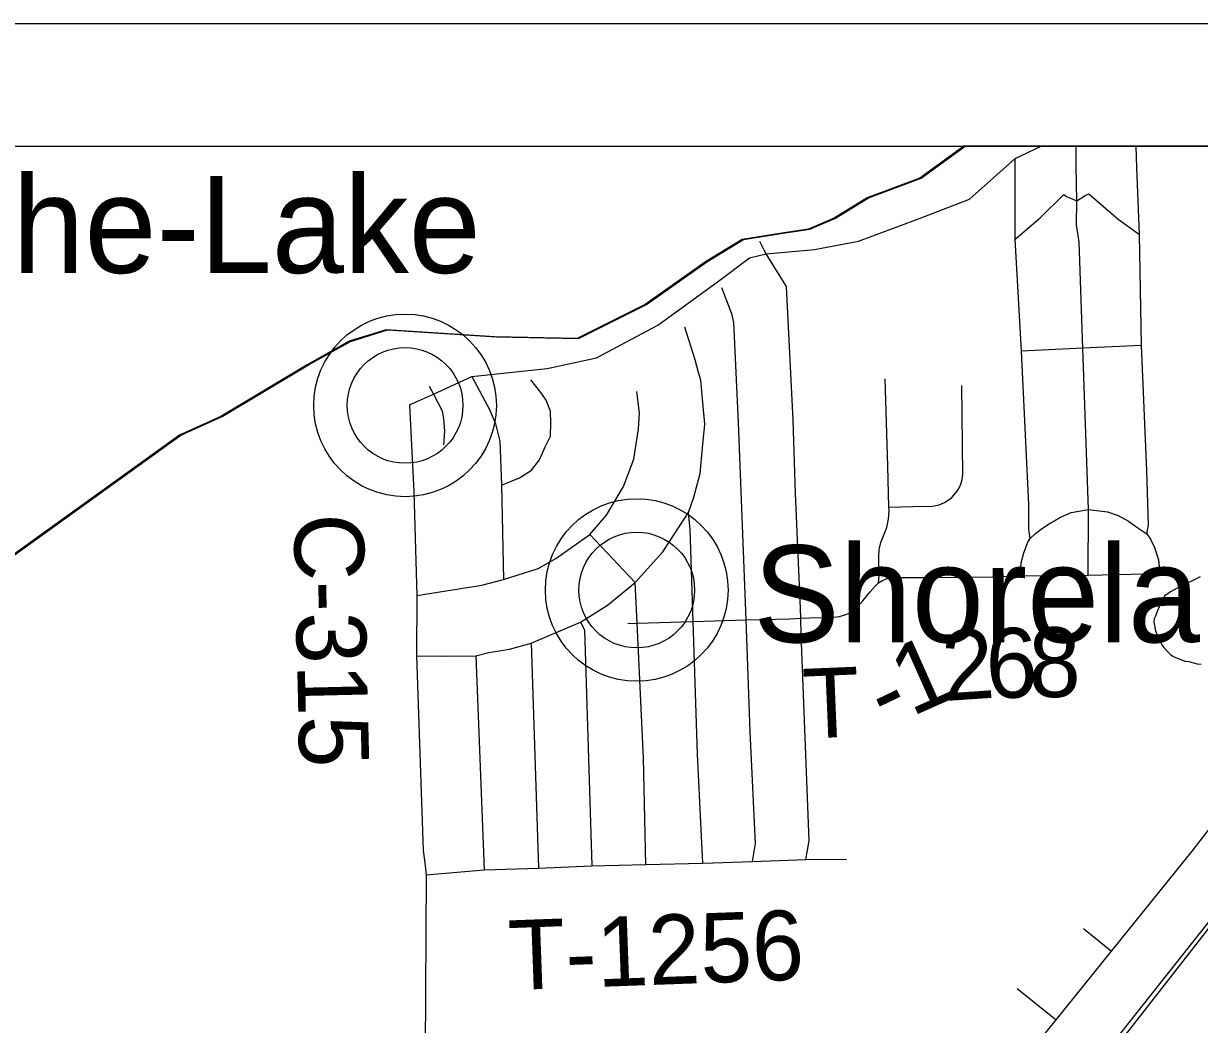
# Model space of a CAD drawing. Extents: x -59 to 82, y -3 to 49.
# Drawn here: x -52.99 to -52.032, y 48.576 to 49.391 of the extents above; entities that cross this region are included whole.
import ezdxf

# ---------------------------------------------------------------- set-up
doc = ezdxf.new("R2010")
doc.units = 0
for name, color, linetype in [('GM_X_Corporation', 7, 'Continuous'), ('GM_X_County_Road_Text', 7, 'Continuous'), ('GM_X_Major_Lake', 7, 'Continuous'), ('GM_X_Minor_River', 7, 'Continuous'), ('GM_X_Rail_Line', 7, 'Continuous'), ('GM_X_Township_Road', 7, 'Continuous'), ('GM_X_Township_Road_Text', 7, 'Continuous'), ('GM_X_Unincorporated', 7, 'Continuous'), ('GM_X_Unincorporated_Location', 7, 'Continuous'), ('GM_X_Unincorporated_Text', 7, 'Continuous'), ('SH_Data', 7, 'Continuous')]:
    doc.layers.add(name, color=color, linetype=linetype)

msp = doc.modelspace()

# ---------------------------------------------------------------- linework, layer by layer
at = {"layer": 'GM_X_Corporation'}
for p, q in [((-52.22423, 49.29125), (-52.26009, 49.26516)), ((-52.22423, 49.29125), (-52.26009, 49.26516)), ((-48.09799, 49.29125), (-52.22423, 49.29125)), ((-50.61637, 49.29125), (-52.22423, 49.29125)), ((-52.26009, 49.26516), (-52.30287, 49.24915)), ((-52.26009, 49.26516), (-52.30287, 49.24915)), ((-52.30287, 49.24915), (-52.32966, 49.23263)), ((-52.30287, 49.24915), (-52.32966, 49.23263)), ((-52.32966, 49.23263), (-52.35068, 49.22367)), ((-52.32966, 49.23263), (-52.35068, 49.22367)), ((-52.37241, 49.22042), (-52.40482, 49.21534)), ((-52.37241, 49.22042), (-52.40482, 49.21534)), ((-52.35068, 49.22367), (-52.37241, 49.22042)), ((-52.35068, 49.22367), (-52.37241, 49.22042)), ((-52.40482, 49.21534), (-52.43467, 49.19695)), ((-52.40482, 49.21534), (-52.43467, 49.19695)), ((-52.43467, 49.19695), (-52.4837, 49.16236)), ((-52.43467, 49.19695), (-52.4837, 49.16236)), ((-52.4837, 49.16236), (-52.53915, 49.13466)), ((-52.4837, 49.16236), (-52.53915, 49.13466)), ((-52.69484, 49.14154), (-52.725, 49.13227)), ((-52.69484, 49.14154), (-52.725, 49.13227)), ((-52.60615, 49.13593), (-52.69484, 49.14154)), ((-52.60615, 49.13593), (-52.69484, 49.14154)), ((-52.53915, 49.13466), (-52.60615, 49.13593)), ((-52.53915, 49.13466), (-52.60615, 49.13593)), ((-52.725, 49.13227), (-52.75904, 49.11315)), ((-52.725, 49.13227), (-52.75904, 49.11315)), ((-52.75904, 49.11315), (-52.82946, 49.07112)), ((-52.75904, 49.11315), (-52.82946, 49.07112)), ((-52.82946, 49.07112), (-52.86309, 49.0558)), ((-52.82946, 49.07112), (-52.86309, 49.0558)), ((-52.86309, 49.0558), (-53.01862, 48.94411)), ((-52.86309, 49.0558), (-53.01862, 48.94411))]:
    msp.add_line(p, q, dxfattribs=at)
at = {"layer": 'GM_X_Major_Lake'}
for p, q in [((-52.25901, 49.26513), (-52.22309, 49.29125)), ((-52.30179, 49.24911), (-52.25901, 49.26513)), ((-52.32858, 49.23259), (-52.30179, 49.24911)), ((-52.3496, 49.22363), (-52.32858, 49.23259)), ((-52.40374, 49.2153), (-52.37133, 49.22038)), ((-52.37133, 49.22038), (-52.3496, 49.22363)), ((-52.43359, 49.19691), (-52.40374, 49.2153)), ((-52.48262, 49.16232), (-52.43359, 49.19691)), ((-52.53807, 49.13462), (-52.48262, 49.16232)), ((-52.72392, 49.13223), (-52.69376, 49.1415)), ((-52.69376, 49.1415), (-52.60508, 49.13589)), ((-52.60508, 49.13589), (-52.53807, 49.13462)), ((-52.75796, 49.11311), (-52.72392, 49.13223)), ((-52.82838, 49.07108), (-52.75796, 49.11311)), ((-52.86201, 49.05576), (-52.82838, 49.07108)), ((-53.01754, 48.94407), (-52.86201, 49.05576))]:
    msp.add_line(p, q, dxfattribs=at)
at = {"layer": 'GM_X_Minor_River'}
for p, q in [((-52.04363, 48.93436), (-52.0474, 48.93238)), ((-52.03156, 48.94031), (-52.04363, 48.93436)), ((-52.05871, 48.92607), (-52.06096, 48.9245)), ((-52.06096, 48.9245), (-52.06092, 48.92222)), ((-52.0557, 48.92803), (-52.05871, 48.92607)), ((-52.05268, 48.92961), (-52.0557, 48.92803)), ((-52.05043, 48.93118), (-52.05268, 48.92961)), ((-52.0474, 48.93238), (-52.05043, 48.93118)), ((-52.0657, 48.91414), (-52.06787, 48.90839)), ((-52.06424, 48.91721), (-52.0657, 48.91414)), ((-52.06092, 48.92222), (-52.06424, 48.91721)), ((-52.06897, 48.90609), (-52.0693, 48.90342)), ((-52.06787, 48.90839), (-52.06897, 48.90609)), ((-52.0693, 48.90342), (-52.06801, 48.89622)), ((-52.06801, 48.89622), (-52.0664, 48.89207)), ((-52.0664, 48.89207), (-52.06282, 48.88492)), ((-52.06282, 48.88492), (-52.06125, 48.88267)), ((-52.06125, 48.88267), (-52.05852, 48.87969)), ((-52.05852, 48.87969), (-52.0558, 48.87709)), ((-52.0558, 48.87709), (-52.05386, 48.8756)), ((-52.05386, 48.8756), (-52.05156, 48.87451)), ((-52.05156, 48.87451), (-52.04388, 48.87163)), ((-52.04388, 48.87163), (-52.04082, 48.87131)), ((-52.04082, 48.87131), (-52.03699, 48.87025)), ((-52.03699, 48.87025), (-52.03393, 48.86955)), ((-52.03393, 48.86955), (-52.03087, 48.86923))]:
    msp.add_line(p, q, dxfattribs=at)
at = {"layer": 'GM_X_Rail_Line'}
for p, q in [((-52.14781, 48.49604), (-51.94583, 48.75479)), ((-52.14538, 48.50651), (-51.96248, 48.7375))]:
    msp.add_line(p, q, dxfattribs=at)
at = {"layer": 'GM_X_Township_Road'}
for p, q in [((-52.18239, 49.28132), (-52.16098, 49.29125)), ((-52.13271, 49.29092), (-52.13278, 49.29125)), ((-52.13247, 49.27499), (-52.13271, 49.29092)), ((-52.08311, 49.27362), (-52.08377, 49.29125)), ((-52.21959, 49.2482), (-52.18239, 49.28132)), ((-52.18231, 49.2319), (-52.18239, 49.28132)), ((-52.13206, 49.24687), (-52.13247, 49.27499)), ((-52.08108, 49.21933), (-52.08311, 49.27362)), ((-52.16187, 49.2328), (-52.1426, 49.25183)), ((-52.1426, 49.25183), (-52.14036, 49.25039)), ((-52.14036, 49.25039), (-52.13206, 49.24687)), ((-52.13206, 49.24687), (-52.12535, 49.25103)), ((-52.12535, 49.25103), (-52.12234, 49.25235)), ((-52.12234, 49.25235), (-52.09845, 49.23193)), ((-52.26312, 49.23127), (-52.21959, 49.2482)), ((-52.13234, 49.22715), (-52.13206, 49.24687)), ((-52.31003, 49.21385), (-52.26312, 49.23127)), ((-52.18228, 49.21542), (-52.18231, 49.2319)), ((-52.18228, 49.21542), (-52.16187, 49.2328)), ((-52.09845, 49.23193), (-52.08108, 49.21933)), ((-52.13016, 49.21325), (-52.13234, 49.22715)), ((-52.38687, 49.20663), (-52.39026, 49.21351)), ((-52.34583, 49.20708), (-52.31003, 49.21385)), ((-52.17707, 49.12419), (-52.18228, 49.21542)), ((-52.12714, 49.12663), (-52.13016, 49.21325)), ((-52.07934, 49.12896), (-52.08108, 49.21933)), ((-52.39878, 49.20035), (-52.38505, 49.20368)), ((-52.38505, 49.20368), (-52.38687, 49.20663)), ((-52.38505, 49.20368), (-52.34583, 49.20708)), ((-52.36914, 49.17778), (-52.38505, 49.20368)), ((-52.42293, 49.18215), (-52.39878, 49.20035)), ((-52.47332, 49.14539), (-52.42293, 49.18215)), ((-52.41275, 49.15392), (-52.42137, 49.17573)), ((-52.36861, 49.17691), (-52.36914, 49.17778)), ((-52.36311, 49.06792), (-52.36861, 49.17691)), ((-52.41144, 49.14758), (-52.41275, 49.15392)), ((-52.52337, 49.11879), (-52.47332, 49.14539)), ((-52.44314, 49.11711), (-52.45137, 49.1437)), ((-52.40779, 49.06611), (-52.41144, 49.14758)), ((-52.12714, 49.12663), (-52.17707, 49.12419)), ((-52.17116, 48.9993), (-52.17707, 49.12419)), ((-52.07934, 49.12896), (-52.12714, 49.12663)), ((-52.12256, 48.99533), (-52.12714, 49.12663)), ((-52.07509, 49.02692), (-52.07934, 49.12896)), ((-52.56361, 49.11004), (-52.52337, 49.11879)), ((-52.44032, 49.10695), (-52.44314, 49.11711)), ((-52.62496, 49.1036), (-52.56361, 49.11004)), ((-52.43853, 49.10048), (-52.44032, 49.10695)), ((-52.65974, 49.09578), (-52.65635, 49.0893)), ((-52.65635, 49.0893), (-52.62496, 49.1036)), ((-52.62496, 49.1036), (-52.61041, 49.0761)), ((-52.5689, 49.09066), (-52.57694, 49.10093)), ((-52.43673, 49.08239), (-52.43853, 49.10048)), ((-52.28609, 49.03048), (-52.28823, 49.10182)), ((-52.22484, 49.02382), (-52.22575, 49.09616)), ((-52.67584, 49.08043), (-52.65635, 49.0893)), ((-52.65635, 49.0893), (-52.64924, 49.07571)), ((-52.56489, 49.08499), (-52.5689, 49.09066)), ((-52.48844, 49.07362), (-52.49056, 49.09128)), ((-52.67584, 49.08043), (-52.6722, 49.00961)), ((-52.56432, 49.08418), (-52.56489, 49.08499)), ((-52.56081, 49.07528), (-52.56432, 49.08418)), ((-52.43518, 49.06482), (-52.43673, 49.08239)), ((-52.64924, 49.07571), (-52.64809, 49.06903)), ((-52.64809, 49.06903), (-52.64717, 49.05913)), ((-52.61041, 49.0761), (-52.60583, 49.06504)), ((-52.56055, 49.06585), (-52.56081, 49.07528)), ((-52.48915, 49.0609), (-52.48844, 49.07362)), ((-52.3614, 49.00834), (-52.36311, 49.06792)), ((-52.64717, 49.05913), (-52.6481, 49.04784)), ((-52.60583, 49.06504), (-52.60205, 49.05102)), ((-52.56081, 49.05506), (-52.56055, 49.06585)), ((-52.49303, 49.03617), (-52.48915, 49.0609)), ((-52.43699, 49.04544), (-52.43518, 49.06482)), ((-52.40152, 48.90541), (-52.40779, 49.06611)), ((-52.60205, 49.05102), (-52.60071, 49.01517)), ((-52.56513, 49.04617), (-52.56081, 49.05506)), ((-52.56998, 49.03565), (-52.56513, 49.04617)), ((-52.43905, 49.02451), (-52.43699, 49.04544)), ((-52.57645, 49.0273), (-52.56998, 49.03565)), ((-52.50151, 49.01391), (-52.49303, 49.03617)), ((-52.2851, 48.99715), (-52.28609, 49.03048)), ((-52.60071, 49.01517), (-52.58615, 49.02109)), ((-52.58615, 49.02109), (-52.57645, 49.0273)), ((-52.44422, 49.00539), (-52.43905, 49.02451)), ((-52.22667, 49.01576), (-52.22547, 49.01966)), ((-52.22547, 49.01966), (-52.22484, 49.02382)), ((-52.07358, 48.98266), (-52.07509, 49.02692)), ((-52.6722, 49.00961), (-52.66968, 48.92502)), ((-52.60071, 49.01517), (-52.59908, 48.93805)), ((-52.51528, 48.9906), (-52.50151, 49.01391)), ((-52.23065, 49.00868), (-52.22855, 49.01181)), ((-52.22855, 49.01181), (-52.22667, 49.01576)), ((-52.44835, 48.99273), (-52.44422, 49.00539)), ((-52.35723, 48.91459), (-52.3614, 49.00834)), ((-52.24413, 48.99907), (-52.23993, 49.00087)), ((-52.23993, 49.00087), (-52.23682, 49.00277)), ((-52.23682, 49.00277), (-52.23398, 49.00505)), ((-52.23398, 49.00505), (-52.23065, 49.00868)), ((-52.52878, 48.97486), (-52.51528, 48.9906)), ((-52.46927, 48.96069), (-52.44835, 48.99273)), ((-52.44706, 48.97878), (-52.44835, 48.99273)), ((-52.2854, 48.98734), (-52.28502, 48.99444)), ((-52.2851, 48.99715), (-52.26562, 48.99773)), ((-52.28502, 48.99444), (-52.2851, 48.99715)), ((-52.26562, 48.99773), (-52.24974, 48.9978)), ((-52.24974, 48.9978), (-52.24413, 48.99907)), ((-52.17107, 48.97931), (-52.17116, 48.9993)), ((-52.14525, 48.98909), (-52.13674, 48.99286)), ((-52.13674, 48.99286), (-52.12256, 48.99533)), ((-52.12294, 48.9416), (-52.12256, 48.99533)), ((-52.12256, 48.99533), (-52.10705, 48.99324)), ((-52.10705, 48.99324), (-52.09835, 48.99022)), ((-52.09835, 48.99022), (-52.09003, 48.98568)), ((-52.28965, 48.97383), (-52.28696, 48.98041)), ((-52.28696, 48.98041), (-52.2854, 48.98734)), ((-52.16095, 48.97944), (-52.15452, 48.9836)), ((-52.15452, 48.9836), (-52.14525, 48.98909)), ((-52.09003, 48.98568), (-52.08228, 48.98038)), ((-52.07509, 48.97527), (-52.07358, 48.98266)), ((-52.5565, 48.95531), (-52.52878, 48.97486)), ((-52.492, 48.93563), (-52.52878, 48.97486)), ((-52.44467, 48.90399), (-52.44706, 48.97878)), ((-52.29184, 48.96836), (-52.28965, 48.97383)), ((-52.17211, 48.96846), (-52.17021, 48.9715)), ((-52.17021, 48.9715), (-52.17107, 48.97931)), ((-52.17021, 48.9715), (-52.16568, 48.97565)), ((-52.16568, 48.97565), (-52.16095, 48.97944)), ((-52.08228, 48.98038), (-52.07509, 48.97527)), ((-52.07509, 48.97527), (-52.07206, 48.97092)), ((-52.07206, 48.97092), (-52.06866, 48.9643)), ((-52.2935, 48.95676), (-52.29313, 48.96263)), ((-52.29313, 48.96263), (-52.29184, 48.96836)), ((-52.17514, 48.95976), (-52.17211, 48.96846)), ((-52.06866, 48.9643), (-52.06544, 48.95428)), ((-52.57105, 48.94722), (-52.5565, 48.95531)), ((-52.492, 48.93563), (-52.46927, 48.96069)), ((-52.29324, 48.94143), (-52.2935, 48.95676)), ((-52.1774, 48.95163), (-52.17514, 48.95976)), ((-52.06544, 48.95428), (-52.0645, 48.94293)), ((-52.59908, 48.93805), (-52.57105, 48.94722)), ((-52.17816, 48.94104), (-52.1774, 48.95163)), ((-52.12294, 48.9416), (-52.0645, 48.94293)), ((-52.66968, 48.92502), (-52.61687, 48.93347)), ((-52.61687, 48.93347), (-52.59908, 48.93805)), ((-52.51433, 48.91723), (-52.492, 48.93563)), ((-52.49041, 48.90249), (-52.492, 48.93563)), ((-52.30055, 48.92814), (-52.29648, 48.93275)), ((-52.29648, 48.93275), (-52.29359, 48.93544)), ((-52.29359, 48.93544), (-52.29324, 48.94143)), ((-52.29359, 48.93544), (-52.29083, 48.9372)), ((-52.29083, 48.9372), (-52.28737, 48.93868)), ((-52.28737, 48.93868), (-52.28306, 48.93958)), ((-52.28306, 48.93958), (-52.27615, 48.93983)), ((-52.27615, 48.93983), (-52.25255, 48.93986)), ((-52.25255, 48.93986), (-52.19886, 48.94038)), ((-52.19886, 48.94038), (-52.17816, 48.94104)), ((-52.17816, 48.94104), (-52.12294, 48.9416)), ((-52.66968, 48.92502), (-52.67021, 48.87588)), ((-52.30653, 48.92089), (-52.30055, 48.92814)), ((-52.53647, 48.90338), (-52.51433, 48.91723)), ((-52.35686, 48.90653), (-52.35723, 48.91459)), ((-52.31378, 48.91312), (-52.31089, 48.91588)), ((-52.31089, 48.91588), (-52.30653, 48.92089)), ((-52.49041, 48.90249), (-52.44467, 48.90399)), ((-52.44467, 48.90399), (-52.40152, 48.90541)), ((-52.44121, 48.79595), (-52.44467, 48.90399)), ((-52.40152, 48.90541), (-52.36567, 48.9062)), ((-52.39824, 48.81431), (-52.40152, 48.90541)), ((-52.36567, 48.9062), (-52.35686, 48.90653)), ((-52.35686, 48.90653), (-52.34975, 48.9068)), ((-52.35653, 48.89367), (-52.35686, 48.90653)), ((-52.34975, 48.9068), (-52.33563, 48.90718)), ((-52.33563, 48.90718), (-52.33052, 48.90759)), ((-52.33052, 48.90759), (-52.32554, 48.90812)), ((-52.32554, 48.90812), (-52.32179, 48.90907)), ((-52.32179, 48.90907), (-52.31933, 48.90983)), ((-52.31933, 48.90983), (-52.31757, 48.91073)), ((-52.31757, 48.91073), (-52.31648, 48.91138)), ((-52.31648, 48.91138), (-52.31378, 48.91312)), ((-52.5767, 48.88628), (-52.53647, 48.90338)), ((-52.53647, 48.90338), (-52.53313, 48.89712)), ((-52.53313, 48.89712), (-52.52714, 48.70482)), ((-52.49801, 48.90224), (-52.49041, 48.90249)), ((-52.48512, 48.79247), (-52.49041, 48.90249)), ((-52.5942, 48.88148), (-52.5767, 48.88628)), ((-52.5767, 48.88628), (-52.57061, 48.70301)), ((-52.35017, 48.72531), (-52.35653, 48.89367)), ((-52.67021, 48.87588), (-52.66457, 48.71721)), ((-52.67021, 48.87588), (-52.64776, 48.87565)), ((-52.64776, 48.87565), (-52.62171, 48.87585)), ((-52.62171, 48.87585), (-52.61108, 48.87878)), ((-52.62171, 48.87585), (-52.615, 48.70144)), ((-52.61108, 48.87878), (-52.5942, 48.88148)), ((-52.39376, 48.72292), (-52.39824, 48.81431)), ((-52.48334, 48.70602), (-52.48512, 48.79247)), ((-52.43827, 48.73435), (-52.44121, 48.79595)), ((-52.43666, 48.70703), (-52.43827, 48.73435)), ((-52.0382, 48.71672), (-52.02113, 48.73838)), ((-52.39644, 48.70829), (-52.39376, 48.72292)), ((-52.35285, 48.71008), (-52.35017, 48.72531)), ((-52.66457, 48.71721), (-52.66333, 48.7073)), ((-52.10374, 48.63531), (-52.0382, 48.71672)), ((-52.66333, 48.7073), (-52.66209, 48.69738)), ((-52.615, 48.70144), (-52.57061, 48.70301)), ((-52.57061, 48.70301), (-52.52714, 48.70482)), ((-52.52714, 48.70482), (-52.48334, 48.70602)), ((-52.48334, 48.70602), (-52.43666, 48.70703)), ((-52.43666, 48.70703), (-52.39644, 48.70829)), ((-52.39644, 48.70829), (-52.35285, 48.71008)), ((-52.35285, 48.71008), (-52.31981, 48.71035)), ((-52.66209, 48.69738), (-52.66358, 48.44397)), ((-52.66209, 48.69738), (-52.615, 48.70144)), ((-52.12658, 48.65376), (-52.10374, 48.63531)), ((-52.14896, 48.57932), (-52.10374, 48.63531)), ((-52.18066, 48.60493), (-52.14896, 48.57932)), ((-52.19358, 48.52409), (-52.14896, 48.57932))]:
    msp.add_line(p, q, dxfattribs=at)
at = {"layer": 'GM_X_Unincorporated'}
for centre, radius in [((-52.67939, 49.08003), 0.0744), ((-52.67939, 49.08003), 0.04716), ((-52.49064, 48.92959), 0.0744), ((-52.49064, 48.92959), 0.04716)]:
    msp.add_circle(centre, radius, dxfattribs=at)
at = {"layer": 'GM_X_Unincorporated_Location'}
for p, q in [((-52.67939, 49.08003), (-52.67939, 49.08003)), ((-52.49064, 48.92959), (-52.49064, 48.92959))]:
    msp.add_line(p, q, dxfattribs=at)
at = {"layer": 'SH_Data'}
for p, q in [((-54.99799, 49.39125), (-47.99799, 49.39125)), ((-54.89799, 49.29125), (-48.09799, 49.29125))]:
    msp.add_line(p, q, dxfattribs=at)

# ---------------------------------------------------------------- texts
at = {"layer": 'GM_X_County_Road_Text'}
msp.add_text('C-315', height=0.056818, rotation=271.35342, dxfattribs=at).set_placement((-52.77021, 48.99134))
at = {"layer": 'GM_X_Township_Road_Text'}
for s, height, rotation, p in [('2', 0.05682, 3.85388, (-52.24002, 48.8391)), ('6', 0.05682, 1.16054, (-52.20581, 48.84143)), ('8', 0.05682, 0.62451, (-52.17096, 48.84213)), ('1', 0.05682, 23.9646, (-52.26691, 48.82615)), ('T', 0.05682, 2.38345, (-52.35422, 48.80846)), ('-', 0.05682, 25.58675, (-52.28757, 48.81625)), ('T-1256', 0.056818, 2.09141, (-52.59419, 48.6035))]:
    msp.add_text(s, height=height, rotation=rotation, dxfattribs=at).set_placement(p)
at = {"layer": 'GM_X_Unincorporated_Text'}
for s, height, p in [('Painesville on-the-Lake', 0.0789773, (-53.7155, 49.18799)), ('Shoreland', 0.078977, (-52.39567, 48.88702))]:
    msp.add_text(s, height=height, rotation=0.00001, dxfattribs=at).set_placement(p)

doc.saveas('drawing.dxf')
